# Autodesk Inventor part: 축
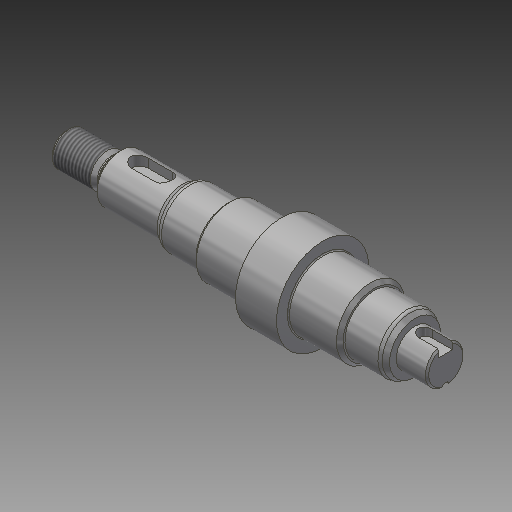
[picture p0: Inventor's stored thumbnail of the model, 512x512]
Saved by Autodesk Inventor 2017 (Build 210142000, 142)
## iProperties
Created: 2019-09
Part Number: 축
Material: 강철, 연강
Document SubType Name: Modeling
Designer: mduedu
Density: 7.86 g/cm^3
Mass: 210.278 g
Surface Area: 69.4764 cm^2
Volume: 26.7529 cm^3
Appearance: 강철
Author: mduedu
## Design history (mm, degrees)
sketch "스케치1"
  geometry: L1 (0, 0)-(15, 0); L2 (15, 0)-(15, 5); L3 (15, 5)-(0, 5); L4 (0, 5)-(0, 0); L5 (15, 0)-(34, 0); L6 (34, 0)-(34, 7); L7 (34, 7)-(15, 7); L8 (15, 7)-(15, 0); L9 (34, 0)-(47, 0); L10 (47, 0)-(47, 8.5); L11 (47, 8.5)-(34, 8.5); L12 (34, 8.5)-(34, 0); L13 (47, 0)-(63, 0); L14 (63, 0)-(63, 10); L15 (63, 10)-(47, 10); L16 (47, 10)-(47, 0); L17 (63, 0)-(75, 0); L18 (75, 0)-(75, 13.5); L19 (75, 13.5)-(63, 13.5); L20 (63, 13.5)-(63, 0); L21 (75, 0)-(90, 0); L22 (90, 0)-(90, 10); L23 (90, 10)-(75, 10); L24 (75, 10)-(75, 0); L25 (90, 0)-(102, 0); L26 (102, 0)-(102, 8.5); L27 (102, 8.5)-(90, 8.5); L28 (90, 8.5)-(90, 0); L29 (102, 0)-(111, 0); L30 (111, 0)-(111, 5.5); L31 (111, 5.5)-(102, 5.5); L32 (102, 5.5)-(102, 0)
  constraints: 64 end point, 16 parallel, 8 horizontal, 8 perpendicular
  dimensions: "d0" = 111 distance between parallel lines of L30 L4; "d2" = 15 distance of L2.end L3.end; "d3" = 19 distance of L6.end L7.end; "d4" = 12 distance of L18.end L19.end; "d5" = 15 distance of L22.end L23.end; "d6" = 12 distance of L26.end L27.end; "d7" = 9 distance of L30.end L31.end; "d8" = 16 distance of L14.end L15.end; "d9" = 10 diameter of L3 L1; "d10" = 14 diameter of L7 L5; "d11" = 17 diameter of L11 L9; "d12" = 20 diameter of L15 L13; "d13" = 27 diameter of L19 L17; "d14" = 20 diameter of L23 L21; "d15" = 17 diameter of L27 L25; "d16" = 11 diameter of L31 L29
revolve "회전1" sketch "스케치1" stored, may be unused: angle "d17" = 90 deg
sketch "스케치2"
  geometry: L1 (0, -5)-(0, 5) reference; L2 (0, 5)-(15, 5) reference; L3 (15, 5)-(15, 7) reference; L4 (15, 7)-(34, 7) reference; L5 (34, 7)-(34, 8.5) reference; L6 (34, 8.5)-(47, 8.5) reference; L7 (47, 8.5)-(47, 10) reference; L8 (47, 10)-(63, 10) reference; L9 (63, 10)-(63, 13.5) reference; L10 (63, 13.5)-(75, 13.5) reference; L11 (75, 13.5)-(75, 10) reference; L12 (75, 10)-(90, 10) reference; L13 (90, 10)-(90, 8.5) reference; L14 (90, 8.5)-(102, 8.5) reference; L15 (102, 8.5)-(102, 5.5) reference; L16 (102, 5.5)-(111, 5.5) reference; L17 (111, 5.5)-(111, -5.5) reference; L18 (111, -5.5)-(102, -5.5) reference; L19 (102, -5.5)-(102, -8.5) reference; L20 (102, -8.5)-(90, -8.5) reference; L21 (90, -8.5)-(90, -10) reference; L22 (90, -10)-(75, -10) reference; L23 (75, -10)-(75, -13.5) reference; L24 (75, -13.5)-(63, -13.5) reference; L25 (63, -13.5)-(63, -10) reference; L26 (63, -10)-(47, -10) reference; L27 (47, -10)-(47, -8.5) reference; L28 (47, -8.5)-(34, -8.5) reference; L29 (34, -8.5)-(34, -7) reference; L30 (34, -7)-(15, -7) reference; L31 (15, -7)-(15, -5) reference; L32 (15, -5)-(0, -5) reference; L33 (0, 0)-(111, 0); L34 (15, 5)-(12.014, 5); L35 (13.4, 4.2)-(15, 4.2); L36 (15, 4.2)-(15, 5); L37 (12.014, 5)-(13.4, 4.2)
  constraints: 10 end point, 1 horizontal, 1 midpoint, 1 parallel, 1 vertical
  dimensions: "d18" = 30 deg angle of L2 L37; "d19" = 8.4 diameter of L35 L33; "d21" = 2.986 distance from line of L34.end L36
revolve "회전2" sketch "스케치2" stored, may be unused: angle "d22" = 90 deg
fillet "모깎기1" dims "d23" = 0.6
feature "스레드1" dims "d24" = 10, "d25" = 0
chamfer "모따기1" distance "d26" = 1; stored, may be unused: second distance "d27" = 2, angle "d28" = 45 deg
chamfer "모따기2" distance "d29" = 1; stored, may be unused: second distance "d30" = 2, angle "d31" = 45 deg
chamfer "모따기3" distance "d32" = 1.819; stored, may be unused: second distance "d33" = 2, angle "d34" = 30 deg
fillet "모깎기2" dims "d35" = 2
chamfer "모따기4" distance "d36" = 1; stored, may be unused: second distance "d37" = 2, angle "d38" = 30 deg
fillet "모깎기3" dims "d39" = 0.3
chamfer "모따기5" distance "d40" = 1; stored, may be unused: second distance "d41" = 2, angle "d42" = 30 deg
chamfer "모따기6" distance "d43" = 1.819; stored, may be unused: second distance "d44" = 2, angle "d45" = 30 deg
chamfer "모따기7" distance "d46" = 0.5; stored, may be unused: second distance "d47" = 2, angle "d48" = 30 deg
fillet "모깎기4" dims "d49" = 2
node "작업 평면1"
sketch "스케치3" dims "d51" = 12
  geometry: L1 (3, -2.5)-(-4, -2.5); L2 (-4, -2.5)-(-4, 2.5); L3 (-4, 2.5)-(3, 2.5); L4 (3, 2.5)-(3, -2.5); L5 (-9.5, 7.45)-(-9.5, -7.45) reference; 3 further points
  constraints: 8 end point, 2 midpoint, 2 parallel, 2 vertical alignment, 1 horizontal, 1 horizontal alignment, 1 perpendicular, 4 other
  dimensions: "d50" = 3 dimension on L5; "d52" = 5 distance between parallel lines of L3 L1
extrude "돌출1" cut sketch "스케치3" distance "d53" = 3; taper "d54" = 0 deg
node "작업 평면3"
sketch "스케치4"
  geometry: L1 (-4.5, -5)-(-4.5, 5) reference; L2 (-4.5, -2)-(1.5, -2); L3 (1.5, -2)-(1.5, 2); L4 (1.5, 2)-(-4.5, 2); L5 (-4.5, 2)-(-4.5, -2); 3 further points
  constraints: 8 end point, 2 horizontal alignment, 2 midpoint, 2 parallel, 1 horizontal, 1 perpendicular, 1 point on line, 1 vertical alignment, 2 other
  dimensions: "d55" = 4 distance between parallel lines of L4 L2; "d57" = 8 dimension on L1
extrude "돌출2" cut sketch "스케치4" distance "d58" = 2.5; taper "d59" = 0 deg
sketch "스케치5"
  geometry: A1 r 5.5 centre (2, -3) between (0, 2.123) and (4, 2.123) reference; 2 further points
  constraints: 1 point on circle
hole "구멍1" sketch "스케치5" at (2, -8.5) diameter "d60" = 2.459; stored, may be unused: countersink angle "d64" = 90 deg, drill point angle "d66" = 118 deg; dims "d61" = 6, "d62" = 4, "d63" = 2, "d65" = 5
node "솔리드1"
node "절단 모서리 투영1"
